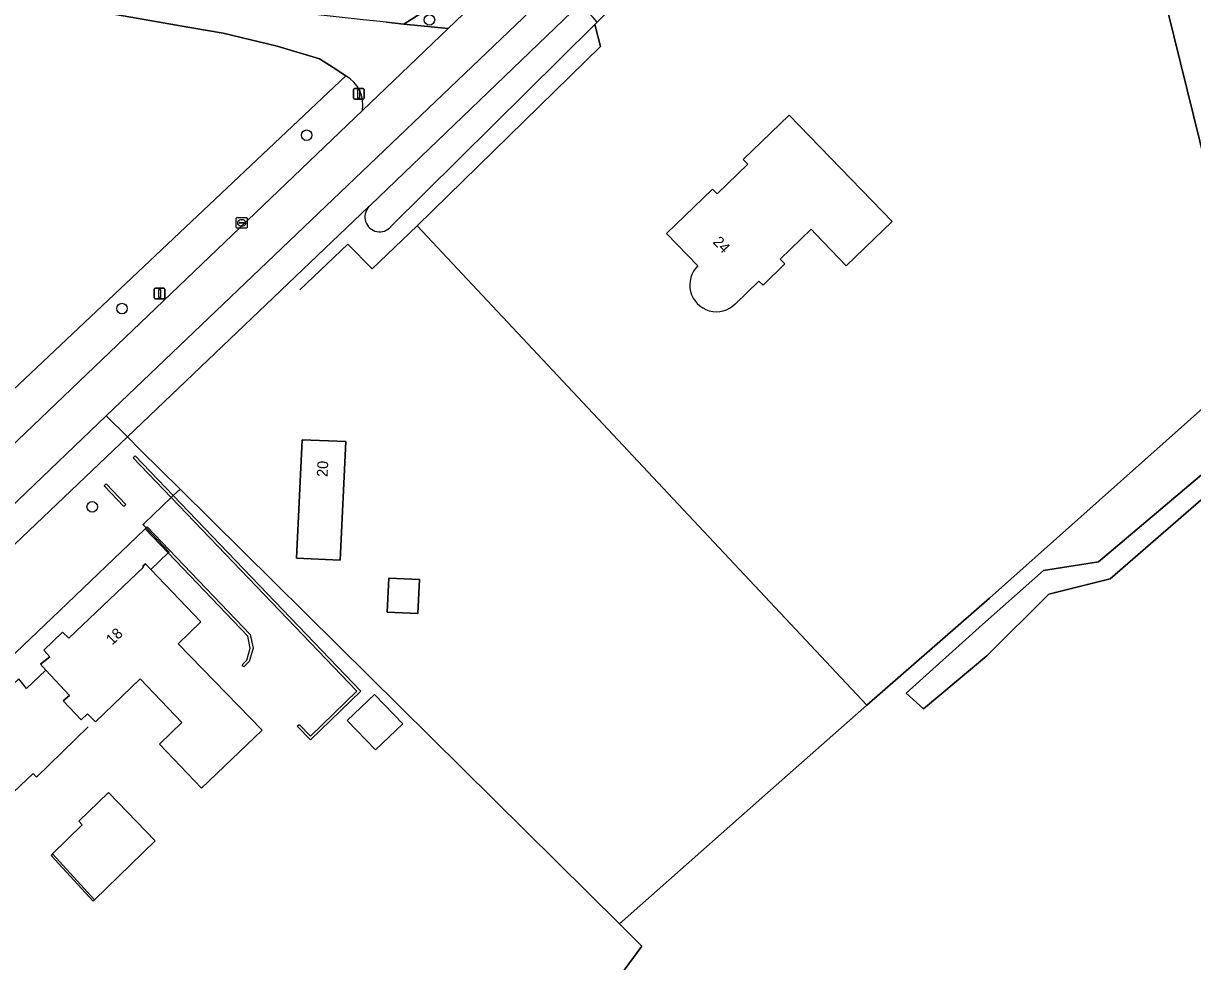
# Model space of a CAD drawing. Extents: x 157132 to 159279, y 384991 to 386650.
# Drawn here: x 157484.6 to 157593.2, y 385940.6 to 386027.8 of the extents above; entities that cross this region are included whole.
import ezdxf

# ---------------------------------------------------------------- set-up
doc = ezdxf.new("R2010")
doc.units = 0
for name, color, linetype in [('IMGEO_Boom', 7, 'Continuous'), ('IMGEO_Brandkraan', 7, 'Continuous'), ('IMGEO_Erf', 7, 'Continuous'), ('IMGEO_Gemengd_bos', 7, 'Continuous'), ('IMGEO_Grasland_overig', 7, 'Continuous'), ('IMGEO_Groenvoorziening', 7, 'Continuous'), ('IMGEO_Hek', 7, 'Continuous'), ('IMGEO_Inrit_open', 7, 'Continuous'), ('IMGEO_Lichtmast', 7, 'Continuous'), ('IMGEO_Loofbos', 7, 'Continuous'), ('IMGEO_Muur', 7, 'Continuous'), ('IMGEO_Pand', 7, 'Continuous'), ('IMGEO_Pand_nummerreeks', 7, 'Continuous'), ('IMGEO_Rijbaan_lokaal_halfverhard', 7, 'Continuous'), ('IMGEO_Rijbaan_lokaal_open', 7, 'Continuous'), ('IMGEO_Waterloop', 7, 'Continuous')]:
    doc.layers.add(name, color=color, linetype=linetype)

msp = doc.modelspace()

# ---------------------------------------------------------------- linework, layer by layer
at = {"layer": 'IMGEO_Boom'}
for centre in [(157522.27, 386028.08), (157510.86, 386017.36), (157493.71, 386001.26), (157490.95, 385982.84)]:
    msp.add_circle(centre, 0.489, dxfattribs=at)
at = {"layer": 'IMGEO_Brandkraan'}
for p, q in [((157504.33, 386008.79), (157504.33, 386009.65)), ((157504.41, 386009.72), (157505.26, 386009.72)), ((157504.82, 386009.5), (157504.85, 386009.5)), ((157505.34, 386009.65), (157505.34, 386008.79)), ((157505.26, 386008.72), (157504.41, 386008.72)), ((157504.59, 386009.21), (157504.59, 386009.23)), ((157505.03, 386009.18), (157504.63, 386009.18)), ((157504.64, 386009.26), (157505.03, 386009.26)), ((157504.84, 386008.94), (157504.82, 386008.94)), ((157505.08, 386009.23), (157505.08, 386009.21))]:
    msp.add_line(p, q, dxfattribs=at)
for points in [[(157504.33, 386008.79), (157504.33, 386009.65)], [(157504.41, 386009.72), (157505.26, 386009.72)], [(157505.34, 386009.65), (157505.34, 386008.79)], [(157505.26, 386008.72), (157504.41, 386008.72)]]:
    msp.add_lwpolyline(points, dxfattribs=at)
for centre, radius, start, end in [((157504.41, 386009.65), 0.0765, 91.552, 178.448), ((157504.41, 386009.65), 0.0765, 91.552, 178.448), ((157505.26, 386009.65), 0.0765, 1.552, 88.448), ((157505.26, 386009.65), 0.0765, 1.552, 88.448), ((157504.41, 386008.8), 0.0765, 181.552, 268.448), ((157504.41, 386008.8), 0.0765, 181.552, 268.448), ((157504.63, 386009.22), 0.0403, 85.8775, 175.7526), ((157504.63, 386009.21), 0.0366, 178.938, 274.7102), ((157505.04, 386009.23), 0.0386, 1.7309, 96.639), ((157505.03, 386009.22), 0.043, 264.8664, 352.4533), ((157505.26, 386008.8), 0.0765, 271.552, 358.448), ((157505.26, 386008.8), 0.0765, 271.552, 358.448)]:
    msp.add_arc(centre, radius, start, end, dxfattribs=at)
for centre, major_axis, ratio, start_param, end_param in [((157504.82, 386009.22), (-0.387, 0.002), 0.722429, 4.712389, 7.853982), ((157504.85, 386009.22), (-0.39, 0.002), 0.717154, 1.570796, 4.712389)]:
    msp.add_ellipse(centre, major_axis=major_axis, ratio=ratio, start_param=start_param, end_param=end_param, dxfattribs=at)
at = {"layer": 'IMGEO_Erf'}
for points in [[(157590.26, 386031.28), (157588.24, 386039.03), (157618.6, 386072.25), (157600.88, 386083.37), (157597.82, 386083.26), (157574.16, 386060.33), (157552.49, 386039.41), (157546.23, 386033.37), (157544.83, 386033.82), (157543.9, 386034.12), (157543.75, 386033.98), (157543.51, 386033.74), (157538.1, 386028.12), (157537.86, 386027.87), (157537.63, 386027.64), (157538.17, 386025.6), (157521.13, 386008.94), (157544.9, 385983.59), (157562.9, 385964.41), (157574.27, 385974.36), (157598.9, 385996.27), (157597.98, 386000)], [(157499.11, 385984.49), (157495.44, 385988.12), (157494.21, 385989.34), (157467.36, 385963.75), (157468, 385963.08), (157468.14, 385962.94), (157469.44, 385964.19), (157475.08, 385958.27), (157474.9, 385958.09), (157469.45, 385963.81), (157445.67, 385940.77), (157512.6, 385902.07), (157541.98, 385942.04), (157539.91, 385944.1)], [(157497.18, 385960.79), (157499.28, 385962.8), (157495.4, 385966.85), (157491.24, 385962.87), (157490.51, 385963.62), (157489.93, 385963.06), (157488.26, 385964.81), (157488.83, 385965.31), (157486.65, 385967.67), (157486.15, 385968.22), (157487.01, 385968.92), (157486.45, 385969.51), (157488.2, 385971.19), (157488.77, 385970.63), (157495.71, 385977.25), (157495.64, 385977.33), (157495.89, 385977.56), (157496.4, 385977.02), (157501.03, 385972.15), (157498.93, 385970.12), (157506.73, 385962.08), (157501.11, 385956.69)], [(157514.63, 385963), (157517.15, 385965.42), (157519.8, 385962.67), (157517.27, 385960.25)]]:
    msp.add_lwpolyline(points, close=True, dxfattribs=at)
for points in [[(157551.84, 386014.68), (157551.42, 386015.11), (157555.67, 386019.22), (157565.24, 386009.36), (157560.98, 386005.24), (157558.16, 386008.16), (157557.71, 386008.63), (157554.84, 386005.86), (157555.29, 386005.4), (157553.25, 386003.42), (157552.86, 386003.81), (157550.66, 386001.68)], [(157547.21, 386005.23), (157544.3, 386008.23), (157548.57, 386012.35), (157548.99, 386011.91), (157551.84, 386014.68)]]:
    msp.add_lwpolyline(points, dxfattribs=at)
msp.add_arc((157548.92, 386003.45), 2.48, 133.8228, 314.6057, dxfattribs=at)
at = {"layer": 'IMGEO_Gemengd_bos'}
for points in [[(157618.6, 386072.25), (157588.24, 386039.03), (157590.26, 386031.28), (157597.98, 386000)], [(157598.9, 385996.27), (157574.27, 385974.36), (157562.9, 385964.41), (157553.95, 385956.53), (157539.91, 385944.1), (157541.98, 385942.04), (157512.6, 385902.07), (157445.67, 385940.77), (157469.45, 385963.81), (157474.9, 385958.09), (157475.08, 385958.27), (157469.44, 385964.19), (157468.14, 385962.94), (157468, 385963.08), (157467.36, 385963.75), (157443.32, 385940.84), (157444.27, 385940.14), (157500, 385908.46), (157548.85, 385880.7), (157597.28, 385853.18)], [(157603.3, 385991.6), (157585.49, 385976.16), (157579.81, 385974.73), (157574.04, 385969), (157568.14, 385964.06), (157566.54, 385965.53), (157573.64, 385971.91), (157579.3, 385976.92), (157584.41, 385977.74), (157602.17, 385992.74)]]:
    msp.add_lwpolyline(points, dxfattribs=at)
at = {"layer": 'IMGEO_Grasland_overig'}
for points in [[(157544.9, 385983.59), (157521.13, 386008.94), (157538.17, 386025.6), (157537.63, 386027.64), (157518.69, 386008.87)], [(157516.62, 386010.7), (157494.21, 385989.34), (157495.44, 385988.12), (157499.11, 385984.49), (157539.91, 385944.1), (157553.95, 385956.53), (157562.9, 385964.41), (157544.9, 385983.59)]]:
    msp.add_lwpolyline(points, dxfattribs=at)
for points in [[(157513.98, 385977.89), (157509.93, 385978.08), (157510.46, 385989.08), (157514.51, 385988.9)], [(157518.48, 385976.21), (157521.35, 385976.08), (157521.2, 385972.92), (157518.35, 385973.06)]]:
    msp.add_lwpolyline(points, close=True, dxfattribs=at)
msp.add_arc((157517.65, 386009.77), 1.38, 138.1284, 318.9492, dxfattribs=at)
at = {"layer": 'IMGEO_Groenvoorziening'}
for points in [[(157522.77, 386029.5), (157519.88, 386027.67), (157524, 386027.27), (157595.68, 386095.83)], [(157211.81, 386074.46), (157213.46, 386068.27), (157211.58, 386069.38), (157211.87, 386068.54), (157226.55, 386059.05), (157238.01, 386052.55), (157275.38, 386031.65), (157325.1, 386002.94), (157371.95, 385976.04), (157409.6, 385954.65), (157433.37, 385941.16), (157433.81, 385941.48), (157436.42, 385943.53), (157438.46, 385945.46), (157516.04, 386019.65)], [(157536.27, 386029.57), (157535.79, 386030.09), (157534.38, 386031.56), (157492.25, 385991.28), (157494.21, 385989.34), (157516.62, 386010.7)], [(157516.79, 386010.86), (157536.27, 386029.57)], [(157514.49, 386022.88), (157480.25, 385990.59), (157470, 385981.06), (157468.65, 385978.5), (157458.43, 385968.62), (157458.4, 385968.59), (157458.36, 385968.55), (157451.13, 385961.92), (157434.59, 385945.98), (157433.99, 385945.4)]]:
    msp.add_lwpolyline(points, dxfattribs=at)
for centre, radius, start, end in [((157513.04, 386020.2), 3.05, 349.5619, 61.5066), ((157517.55, 386009.88), 1.24, 127.8047, 138.7654)]:
    msp.add_arc(centre, radius, start, end, dxfattribs=at)
at = {"layer": 'IMGEO_Hek'}
for points in [[(157543.9, 386034.12), (157544.83, 386033.82), (157546.23, 386033.37), (157552.49, 386039.41), (157574.16, 386060.33), (157597.82, 386083.26), (157600.88, 386083.37), (157618.6, 386072.25), (157588.24, 386039.03), (157590.26, 386031.28), (157597.98, 386000), (157598.9, 385996.27), (157574.27, 385974.36), (157562.9, 385964.41)], [(157537.63, 386027.64), (157538.17, 386025.6), (157521.13, 386008.94)], [(157510.22, 386003), (157514.7, 386007.25), (157516.95, 386004.96), (157521.13, 386008.94)], [(157521.13, 386008.94), (157544.9, 385983.59), (157562.9, 385964.41)], [(157495.44, 385988.12), (157499.11, 385984.49)], [(157498.47, 385983.88), (157499.11, 385984.49)], [(157539.91, 385944.1), (157499.11, 385984.49)], [(157495.76, 385981.29), (157498.29, 385983.71)], [(157498.29, 385983.71), (157498.47, 385983.88)], [(157495.96, 385980.88), (157495.66, 385981.2), (157495.76, 385981.29)], [(157498.01, 385978.56), (157498.09, 385978.63), (157495.96, 385980.88)], [(157496.4, 385977.02), (157498.01, 385978.56)], [(157486.65, 385967.67), (157484.83, 385965.96), (157484.12, 385966.86), (157477.39, 385960.46)], [(157475.08, 385958.27), (157474.9, 385958.09), (157469.45, 385963.81), (157445.67, 385940.77), (157512.6, 385902.07), (157541.98, 385942.04), (157539.91, 385944.1)], [(157562.9, 385964.41), (157553.95, 385956.53), (157539.91, 385944.1)]]:
    msp.add_lwpolyline(points, dxfattribs=at)
at = {"layer": 'IMGEO_Inrit_open'}
for points in [[(157524, 386027.27), (157519.88, 386027.67), (157518.28, 386027.87), (157516.12, 386028.09), (157511.11, 386028.64), (157504.95, 386029.42), (157500, 386029.98), (157486.96, 386032.1), (157471.52, 386035.08), (157470.89, 386032.16), (157473.92, 386032.25), (157478.32, 386031.51), (157488.17, 386029.45), (157500, 386027.38), (157503.12, 386026.83), (157508.13, 386025.63), (157512.05, 386024.46), (157513.32, 386023.65), (157514.49, 386022.88)], [(157516.04, 386019.65), (157524, 386027.27)]]:
    msp.add_lwpolyline(points, dxfattribs=at)
msp.add_arc((157513.04, 386020.2), 3.05, 349.5619, 61.5066, dxfattribs=at)
at = {"layer": 'IMGEO_Lichtmast'}
for p, q in [((157515.21, 386020.8), (157515.21, 386021.6)), ((157515.21, 386021.6), (157515.21, 386020.8)), ((157515.31, 386021.7), (157516.1, 386021.7)), ((157516.1, 386021.7), (157515.31, 386021.7)), ((157516.2, 386021.6), (157516.2, 386020.8)), ((157516.2, 386020.8), (157516.2, 386021.6)), ((157516.1, 386020.7), (157515.31, 386020.7)), ((157515.31, 386020.7), (157516.1, 386020.7)), ((157496.71, 386002.26), (157496.71, 386003.06)), ((157496.71, 386003.06), (157496.71, 386002.26)), ((157496.81, 386003.16), (157497.6, 386003.16)), ((157497.6, 386003.16), (157496.81, 386003.16)), ((157497.7, 386003.06), (157497.7, 386002.26)), ((157497.7, 386002.26), (157497.7, 386003.06)), ((157497.6, 386002.16), (157496.81, 386002.16)), ((157496.81, 386002.16), (157497.6, 386002.16))]:
    msp.add_line(p, q, dxfattribs=at)
for points in [[(157515.63, 386021.57), (157515.78, 386021.57), (157515.78, 386020.82), (157515.63, 386020.82), (157515.63, 386021.57)], [(157497.13, 386003.03), (157497.28, 386003.03), (157497.28, 386002.28), (157497.13, 386002.28), (157497.13, 386003.03)]]:
    msp.add_lwpolyline(points, dxfattribs=at)
for centre, start, end in [((157515.31, 386021.6), 90, 180), ((157515.31, 386021.6), 90, 180), ((157516.1, 386021.6), 0, 90), ((157516.1, 386021.6), 360, 90), ((157515.31, 386020.8), 180, 270), ((157515.31, 386020.8), 180, 270), ((157516.1, 386020.8), 270, 0), ((157516.1, 386020.8), 270, 0), ((157496.81, 386003.06), 90, 180), ((157496.81, 386003.06), 90, 180), ((157497.6, 386003.06), 0, 90), ((157497.6, 386003.06), 360, 90), ((157496.81, 386002.26), 180, 270), ((157496.81, 386002.26), 180, 270), ((157497.6, 386002.26), 270, 0), ((157497.6, 386002.26), 270, 0)]:
    msp.add_arc(centre, 0.1, start, end, dxfattribs=at)
at = {"layer": 'IMGEO_Loofbos'}
for points in [[(157468.65, 385978.5), (157470, 385981.06), (157480.25, 385990.59), (157514.49, 386022.88), (157513.32, 386023.65), (157512.05, 386024.46), (157508.13, 386025.63), (157503.12, 386026.83), (157500, 386027.38), (157488.17, 386029.45)], [(157518.28, 386027.87), (157519.88, 386027.67), (157522.77, 386029.5)]]:
    msp.add_lwpolyline(points, dxfattribs=at)
at = {"layer": 'IMGEO_Muur'}
for points in [[(157494.74, 385987.4), (157494.93, 385987.57)], [(157498.29, 385983.71), (157494.74, 385987.4)], [(157494.93, 385987.57), (157498.47, 385983.88)], [(157492.05, 385984.79), (157492.23, 385984.98)], [(157493.89, 385982.87), (157492.05, 385984.79)], [(157492.23, 385984.98), (157494.08, 385983.05)], [(157510.18, 385962.63), (157511.22, 385961.54), (157515.53, 385965.71), (157498.29, 385983.71)], [(157498.47, 385983.88), (157515.88, 385965.7), (157511.22, 385961.18), (157509.99, 385962.45), (157510.18, 385962.63)], [(157494.08, 385983.05), (157493.89, 385982.87)], [(157495.87, 385980.8), (157495.05, 385980.01)], [(157495.87, 385980.8), (157495.96, 385980.88)], [(157498.01, 385978.56), (157495.87, 385980.8)], [(157495.96, 385980.88), (157496.06, 385980.98)], [(157496.06, 385980.98), (157505.61, 385970.99), (157505.9, 385969.72), (157505.53, 385968.46), (157505.04, 385967.99)], [(157495.05, 385980.01), (157490.83, 385975.96)], [(157505.04, 385967.99), (157504.87, 385968.17), (157505.3, 385968.59), (157505.62, 385969.71), (157505.41, 385970.83), (157498.01, 385978.56)], [(157490.83, 385975.96), (157487.91, 385973.19)], [(157487.91, 385973.19), (157482.49, 385968.01)], [(157477.39, 385960.46), (157482.44, 385955.19), (157485.45, 385958.08), (157485.77, 385957.73), (157490.58, 385962.39)], [(157487.26, 385950.6), (157490, 385953.29), (157489.7, 385953.63), (157492.47, 385956.31), (157496.8, 385951.82), (157491.17, 385946.34)], [(157487.26, 385950.6), (157487.12, 385950.46), (157491.02, 385946.21), (157491.17, 385946.34)], [(157491.17, 385946.34), (157487.26, 385950.6)]]:
    msp.add_lwpolyline(points, dxfattribs=at)
at = {"layer": 'IMGEO_Pand'}
msp.add_lwpolyline([(157550.66, 386001.68), (157552.86, 386003.81), (157553.25, 386003.42), (157555.29, 386005.4), (157554.84, 386005.86), (157557.71, 386008.63), (157558.16, 386008.16), (157560.98, 386005.24), (157565.24, 386009.36), (157555.67, 386019.22), (157551.42, 386015.11), (157551.84, 386014.68), (157548.99, 386011.91), (157548.57, 386012.35), (157544.3, 386008.23), (157547.21, 386005.23)], dxfattribs=at)
for points in [[(157514.51, 385988.9), (157510.46, 385989.08), (157509.93, 385978.08), (157513.98, 385977.89)], [(157486.65, 385967.67), (157488.83, 385965.31), (157488.26, 385964.81), (157489.93, 385963.06), (157490.51, 385963.62), (157491.24, 385962.87), (157495.4, 385966.85), (157499.28, 385962.8), (157497.18, 385960.79), (157501.11, 385956.69), (157506.73, 385962.08), (157498.93, 385970.12), (157501.03, 385972.15), (157496.4, 385977.02), (157495.89, 385977.56), (157495.64, 385977.33), (157495.71, 385977.25), (157488.77, 385970.63), (157488.2, 385971.19), (157486.45, 385969.51), (157487.01, 385968.92), (157486.15, 385968.22)], [(157518.48, 385976.21), (157518.35, 385973.06), (157521.2, 385972.92), (157521.35, 385976.08)], [(157514.63, 385963), (157517.27, 385960.25), (157519.8, 385962.67), (157517.15, 385965.42)]]:
    msp.add_lwpolyline(points, close=True, dxfattribs=at)
msp.add_arc((157548.92, 386003.45), 2.48, 133.8228, 314.6057, dxfattribs=at)
at = {"layer": 'IMGEO_Rijbaan_lokaal_halfverhard'}
msp.add_lwpolyline([(157494.21, 385989.34), (157492.25, 385991.28), (157465.49, 385965.68), (157467.36, 385963.75)], close=True, dxfattribs=at)
at = {"layer": 'IMGEO_Rijbaan_lokaal_open'}
msp.add_lwpolyline([(157534.38, 386031.56), (157540.48, 386037.39), (157593.7, 386088.29), (157605.01, 386099.14), (157605.13, 386099.14), (157608.16, 386102.26), (157605.48, 386105.15), (157600.57, 386099.84), (157599.53, 386099.49), (157595.68, 386095.83), (157524, 386027.27), (157516.04, 386019.65), (157438.46, 385945.46), (157436.42, 385943.53), (157433.81, 385941.48), (157433.37, 385941.16), (157438.31, 385938.26), (157438.46, 385938.6), (157438.94, 385939.63), (157441.44, 385942.69), (157465.49, 385965.68), (157492.25, 385991.28)], close=True, dxfattribs=at)
at = {"layer": 'IMGEO_Waterloop'}
for points in [[(157537.63, 386027.64), (157537.86, 386027.87), (157537.46, 386028.29), (157536.27, 386029.57), (157516.79, 386010.86)], [(157518.69, 386008.87), (157537.63, 386027.64)], [(157602.17, 385992.74), (157584.41, 385977.74), (157579.3, 385976.92), (157573.64, 385971.91), (157566.54, 385965.53), (157568.14, 385964.06), (157574.04, 385969), (157579.81, 385974.73), (157585.49, 385976.16), (157603.3, 385991.6)]]:
    msp.add_lwpolyline(points, dxfattribs=at)
for centre, radius, start, end in [((157517.65, 386009.77), 1.38, 138.1284, 318.9492), ((157517.55, 386009.88), 1.24, 127.8047, 138.7654)]:
    msp.add_arc(centre, radius, start, end, dxfattribs=at)

# ---------------------------------------------------------------- texts
at = {"layer": 'IMGEO_Pand_nummerreeks'}
for s, rotation, p in [('24', 314.0774, (157548.53, 386007.39)), ('20', 87.2386, (157512.8, 385985.6)), ('18', 43.6846, (157492.8, 385969.94))]:
    msp.add_text(s, height=1, rotation=rotation, dxfattribs=at).set_placement(p)

doc.saveas('drawing.dxf')
